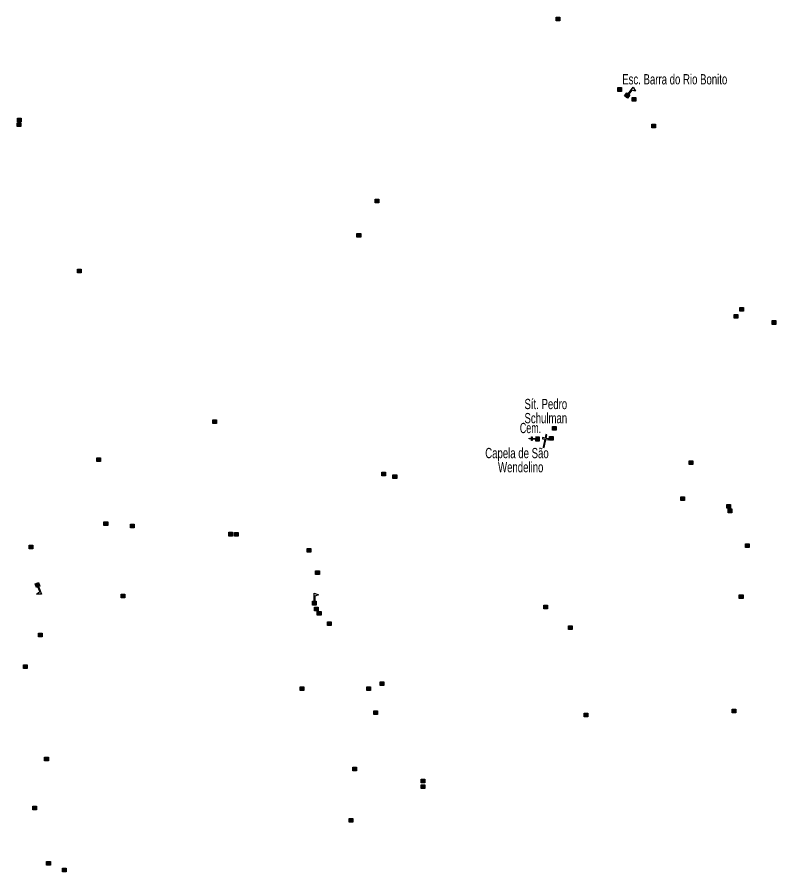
# Model space of a CAD drawing. Extents: x 647.8 to 672.9, y 6929.3 to 6957.3.
# Drawn here: x 648.14 to 654.07, y 6943.68 to 6950.35 of the extents above; entities that cross this region are included whole.
import ezdxf
from ezdxf.enums import TextEntityAlignment as Align

# ---------------------------------------------------------------- set-up
doc = ezdxf.new("R2010")
doc.units = 0
doc.header["$LTSCALE"] = 0.032
for name, color, linetype, lineweight in [('2', 7, 'Continuous', 25), ('20', 7, 'Continuous', 25), ('4', 7, 'Continuous', 25), ('6', 7, 'Continuous', 25)]:
    doc.layers.add(name, color=color, linetype=linetype, lineweight=lineweight)
doc.layers.add('61', color=7, linetype='Continuous')

msp = doc.modelspace()

# ---------------------------------------------------------------- hatches: boundary and pattern name
at = {"layer": '2'}
for points in [[(652.3521, 6950.3524), (652.3811, 6950.3524), (652.3811, 6950.3234), (652.3521, 6950.3234)], [(652.8326, 6949.8018), (652.8616, 6949.8018), (652.8616, 6949.7728), (652.8326, 6949.7728)], [(652.9445, 6949.725), (652.9735, 6949.725), (652.9735, 6949.696), (652.9445, 6949.696)], [(648.1465, 6949.5648), (648.1755, 6949.5648), (648.1755, 6949.5358), (648.1465, 6949.5358)], [(648.1443, 6949.5275), (648.1733, 6949.5275), (648.1733, 6949.4985), (648.1443, 6949.4985)], [(653.098, 6949.5166), (653.127, 6949.5166), (653.127, 6949.4876), (653.098, 6949.4876)], [(650.9393, 6948.9308), (650.9683, 6948.9308), (650.9683, 6948.9018), (650.9393, 6948.9018)], [(650.7967, 6948.6631), (650.8257, 6948.6631), (650.8257, 6948.6341), (650.7967, 6948.6341)], [(648.616, 6948.3845), (648.645, 6948.3845), (648.645, 6948.3555), (648.616, 6948.3555)], [(653.7408, 6948.0313), (653.7698, 6948.0313), (653.7698, 6948.0023), (653.7408, 6948.0023)], [(653.7847, 6948.0862), (653.8137, 6948.0862), (653.8137, 6948.0572), (653.7847, 6948.0572)], [(654.037, 6947.9831), (654.066, 6947.9831), (654.066, 6947.9541), (654.037, 6947.9541)], [(649.6712, 6947.2086), (649.7002, 6947.2086), (649.7002, 6947.1796), (649.6712, 6947.1796)], [(652.3214, 6947.156), (652.3504, 6947.156), (652.3504, 6947.127), (652.3214, 6947.127)], [(652.2995, 6947.0792), (652.3285, 6947.0792), (652.3285, 6947.0502), (652.2995, 6947.0502)], [(648.7674, 6946.9125), (648.7964, 6946.9125), (648.7964, 6946.8835), (648.7674, 6946.8835)], [(653.3898, 6946.8883), (653.4188, 6946.8883), (653.4188, 6946.8593), (653.3898, 6946.8593)], [(650.9897, 6946.8006), (651.0187, 6946.8006), (651.0187, 6946.7716), (650.9897, 6946.7716)], [(651.0775, 6946.7808), (651.1065, 6946.7808), (651.1065, 6946.7518), (651.0775, 6946.7518)], [(653.324, 6946.6075), (653.353, 6946.6075), (653.353, 6946.5785), (653.324, 6946.5785)], [(653.6838, 6946.5483), (653.7128, 6946.5483), (653.7128, 6946.5193), (653.6838, 6946.5193)], [(653.6926, 6946.5132), (653.7216, 6946.5132), (653.7216, 6946.4842), (653.6926, 6946.4842)], [(648.8222, 6946.4123), (648.8512, 6946.4123), (648.8512, 6946.3833), (648.8222, 6946.3833)], [(649.0284, 6946.3947), (649.0574, 6946.3947), (649.0574, 6946.3657), (649.0284, 6946.3657)], [(649.7963, 6946.3311), (649.8253, 6946.3311), (649.8253, 6946.3021), (649.7963, 6946.3021)], [(649.8402, 6946.3289), (649.8692, 6946.3289), (649.8692, 6946.2999), (649.8402, 6946.2999)], [(648.2387, 6946.2302), (648.2677, 6946.2302), (648.2677, 6946.2012), (648.2387, 6946.2012)], [(653.8286, 6946.2411), (653.8576, 6946.2411), (653.8576, 6946.2121), (653.8286, 6946.2121)], [(650.4084, 6946.2038), (650.4374, 6946.2038), (650.4374, 6946.1748), (650.4084, 6946.1748)], [(650.4742, 6946.0305), (650.5032, 6946.0305), (650.5032, 6946.0015), (650.4742, 6946.0015)], [(648.957, 6945.8475), (648.986, 6945.8475), (648.986, 6945.8185), (648.957, 6945.8185)], [(653.7803, 6945.8441), (653.8093, 6945.8441), (653.8093, 6945.8151), (653.7803, 6945.8151)], [(652.2556, 6945.7629), (652.2846, 6945.7629), (652.2846, 6945.7339), (652.2556, 6945.7339)], [(650.4654, 6945.7475), (650.4944, 6945.7475), (650.4944, 6945.7185), (650.4654, 6945.7185)], [(650.4873, 6945.7124), (650.5163, 6945.7124), (650.5163, 6945.6834), (650.4873, 6945.6834)], [(650.5663, 6945.6334), (650.5953, 6945.6334), (650.5953, 6945.6044), (650.5663, 6945.6044)], [(652.4465, 6945.6005), (652.4755, 6945.6005), (652.4755, 6945.5715), (652.4465, 6945.5715)], [(648.3111, 6945.5435), (648.3401, 6945.5435), (648.3401, 6945.5145), (648.3111, 6945.5145)], [(648.1948, 6945.2978), (648.2238, 6945.2978), (648.2238, 6945.2688), (648.1948, 6945.2688)], [(650.9766, 6945.164), (651.0056, 6945.164), (651.0056, 6945.135), (650.9766, 6945.135)], [(650.3535, 6945.1245), (650.3825, 6945.1245), (650.3825, 6945.0955), (650.3535, 6945.0955)], [(650.8735, 6945.1245), (650.9025, 6945.1245), (650.9025, 6945.0955), (650.8735, 6945.0955)], [(650.9283, 6944.938), (650.9573, 6944.938), (650.9573, 6944.909), (650.9283, 6944.909)], [(652.5693, 6944.9204), (652.5983, 6944.9204), (652.5983, 6944.8914), (652.5693, 6944.8914)], [(653.7255, 6944.9512), (653.7545, 6944.9512), (653.7545, 6944.9222), (653.7255, 6944.9222)], [(648.3593, 6944.576), (648.3883, 6944.576), (648.3883, 6944.547), (648.3593, 6944.547)], [(650.7638, 6944.497), (650.7928, 6944.497), (650.7928, 6944.468), (650.7638, 6944.468)], [(651.2969, 6944.4049), (651.3259, 6944.4049), (651.3259, 6944.3759), (651.2969, 6944.3759)], [(651.2969, 6944.361), (651.3259, 6944.361), (651.3259, 6944.332), (651.2969, 6944.332)], [(648.2672, 6944.1943), (648.2962, 6944.1943), (648.2962, 6944.1653), (648.2672, 6944.1653)], [(650.7353, 6944.0978), (650.7643, 6944.0978), (650.7643, 6944.0688), (650.7353, 6944.0688)], [(648.3747, 6943.7621), (648.4037, 6943.7621), (648.4037, 6943.7331), (648.3747, 6943.7331)], [(648.4975, 6943.7094), (648.5265, 6943.7094), (648.5265, 6943.6804), (648.4975, 6943.6804)]]:
    msp.add_hatch(color=256, dxfattribs=at).paths.add_polyline_path(points)
at = {"layer": '4'}
for points in [[(652.8849, 6949.7385), (652.9032, 6949.7623), (652.927, 6949.7441), (652.9087, 6949.7203)], [(648.3122, 6945.9399), (648.3229, 6945.9119), (648.2949, 6945.901), (648.2841, 6945.929)], [(650.4492, 6945.7634), (650.4492, 6945.7934), (650.4792, 6945.7934), (650.4792, 6945.7634)]]:
    msp.add_hatch(color=256, dxfattribs=at).paths.add_polyline_path(points)
at = {"layer": '6'}
for points in [[(652.1912, 6947.0629), (652.191, 6947.0579), (652.1635, 6947.0591), (652.163, 6947.0466), (652.158, 6947.0468), (652.1585, 6947.0593), (652.141, 6947.0599), (652.1412, 6947.0649), (652.1587, 6947.0643), (652.1593, 6947.0767), (652.1643, 6947.0765), (652.1637, 6947.064)], [(652.1905, 6947.0454), (652.2204, 6947.0441), (652.2217, 6947.0741), (652.1917, 6947.0754)]]:
    msp.add_hatch(color=256, dxfattribs=at).paths.add_polyline_path(points)

# ---------------------------------------------------------------- linework, layer by layer
at = {"layer": '2'}
for points in [[(652.3521, 6950.3524), (652.3811, 6950.3524), (652.3811, 6950.3234), (652.3521, 6950.3234)], [(652.8326, 6949.8018), (652.8616, 6949.8018), (652.8616, 6949.7728), (652.8326, 6949.7728)], [(652.9445, 6949.725), (652.9735, 6949.725), (652.9735, 6949.696), (652.9445, 6949.696)], [(648.1465, 6949.5648), (648.1755, 6949.5648), (648.1755, 6949.5358), (648.1465, 6949.5358)], [(648.1443, 6949.5275), (648.1733, 6949.5275), (648.1733, 6949.4985), (648.1443, 6949.4985)], [(653.098, 6949.5166), (653.127, 6949.5166), (653.127, 6949.4876), (653.098, 6949.4876)], [(650.9393, 6948.9308), (650.9683, 6948.9308), (650.9683, 6948.9018), (650.9393, 6948.9018)], [(650.7967, 6948.6631), (650.8257, 6948.6631), (650.8257, 6948.6341), (650.7967, 6948.6341)], [(648.616, 6948.3845), (648.645, 6948.3845), (648.645, 6948.3555), (648.616, 6948.3555)], [(653.7408, 6948.0313), (653.7698, 6948.0313), (653.7698, 6948.0023), (653.7408, 6948.0023)], [(653.7847, 6948.0862), (653.8137, 6948.0862), (653.8137, 6948.0572), (653.7847, 6948.0572)], [(654.037, 6947.9831), (654.066, 6947.9831), (654.066, 6947.9541), (654.037, 6947.9541)], [(649.6712, 6947.2086), (649.7002, 6947.2086), (649.7002, 6947.1796), (649.6712, 6947.1796)], [(652.3214, 6947.156), (652.3504, 6947.156), (652.3504, 6947.127), (652.3214, 6947.127)], [(652.2995, 6947.0792), (652.3285, 6947.0792), (652.3285, 6947.0502), (652.2995, 6947.0502)], [(648.7674, 6946.9125), (648.7964, 6946.9125), (648.7964, 6946.8835), (648.7674, 6946.8835)], [(653.3898, 6946.8883), (653.4188, 6946.8883), (653.4188, 6946.8593), (653.3898, 6946.8593)], [(650.9897, 6946.8006), (651.0187, 6946.8006), (651.0187, 6946.7716), (650.9897, 6946.7716)], [(651.0775, 6946.7808), (651.1065, 6946.7808), (651.1065, 6946.7518), (651.0775, 6946.7518)], [(653.324, 6946.6075), (653.353, 6946.6075), (653.353, 6946.5785), (653.324, 6946.5785)], [(653.6838, 6946.5483), (653.7128, 6946.5483), (653.7128, 6946.5193), (653.6838, 6946.5193)], [(653.6926, 6946.5132), (653.7216, 6946.5132), (653.7216, 6946.4842), (653.6926, 6946.4842)], [(648.8222, 6946.4123), (648.8512, 6946.4123), (648.8512, 6946.3833), (648.8222, 6946.3833)], [(649.0284, 6946.3947), (649.0574, 6946.3947), (649.0574, 6946.3657), (649.0284, 6946.3657)], [(649.7963, 6946.3311), (649.8253, 6946.3311), (649.8253, 6946.3021), (649.7963, 6946.3021)], [(649.8402, 6946.3289), (649.8692, 6946.3289), (649.8692, 6946.2999), (649.8402, 6946.2999)], [(648.2387, 6946.2302), (648.2677, 6946.2302), (648.2677, 6946.2012), (648.2387, 6946.2012)], [(653.8286, 6946.2411), (653.8576, 6946.2411), (653.8576, 6946.2121), (653.8286, 6946.2121)], [(650.4084, 6946.2038), (650.4374, 6946.2038), (650.4374, 6946.1748), (650.4084, 6946.1748)], [(650.4742, 6946.0305), (650.5032, 6946.0305), (650.5032, 6946.0015), (650.4742, 6946.0015)], [(648.957, 6945.8475), (648.986, 6945.8475), (648.986, 6945.8185), (648.957, 6945.8185)], [(653.7803, 6945.8441), (653.8093, 6945.8441), (653.8093, 6945.8151), (653.7803, 6945.8151)], [(652.2556, 6945.7629), (652.2846, 6945.7629), (652.2846, 6945.7339), (652.2556, 6945.7339)], [(650.4654, 6945.7475), (650.4944, 6945.7475), (650.4944, 6945.7185), (650.4654, 6945.7185)], [(650.4873, 6945.7124), (650.5163, 6945.7124), (650.5163, 6945.6834), (650.4873, 6945.6834)], [(650.5663, 6945.6334), (650.5953, 6945.6334), (650.5953, 6945.6044), (650.5663, 6945.6044)], [(652.4465, 6945.6005), (652.4755, 6945.6005), (652.4755, 6945.5715), (652.4465, 6945.5715)], [(648.3111, 6945.5435), (648.3401, 6945.5435), (648.3401, 6945.5145), (648.3111, 6945.5145)], [(648.1948, 6945.2978), (648.2238, 6945.2978), (648.2238, 6945.2688), (648.1948, 6945.2688)], [(650.9766, 6945.164), (651.0056, 6945.164), (651.0056, 6945.135), (650.9766, 6945.135)], [(650.3535, 6945.1245), (650.3825, 6945.1245), (650.3825, 6945.0955), (650.3535, 6945.0955)], [(650.8735, 6945.1245), (650.9025, 6945.1245), (650.9025, 6945.0955), (650.8735, 6945.0955)], [(650.9283, 6944.938), (650.9573, 6944.938), (650.9573, 6944.909), (650.9283, 6944.909)], [(652.5693, 6944.9204), (652.5983, 6944.9204), (652.5983, 6944.8914), (652.5693, 6944.8914)], [(653.7255, 6944.9512), (653.7545, 6944.9512), (653.7545, 6944.9222), (653.7255, 6944.9222)], [(648.3593, 6944.576), (648.3883, 6944.576), (648.3883, 6944.547), (648.3593, 6944.547)], [(650.7638, 6944.497), (650.7928, 6944.497), (650.7928, 6944.468), (650.7638, 6944.468)], [(651.2969, 6944.4049), (651.3259, 6944.4049), (651.3259, 6944.3759), (651.2969, 6944.3759)], [(651.2969, 6944.361), (651.3259, 6944.361), (651.3259, 6944.332), (651.2969, 6944.332)], [(648.2672, 6944.1943), (648.2962, 6944.1943), (648.2962, 6944.1653), (648.2672, 6944.1653)], [(650.7353, 6944.0978), (650.7643, 6944.0978), (650.7643, 6944.0688), (650.7353, 6944.0688)], [(648.3747, 6943.7621), (648.4037, 6943.7621), (648.4037, 6943.7331), (648.3747, 6943.7331)], [(648.4975, 6943.7094), (648.5265, 6943.7094), (648.5265, 6943.6804), (648.4975, 6943.6804)]]:
    msp.add_lwpolyline(points, close=True, dxfattribs=at)
at = {"layer": '20'}
for points in [[(652.2725, 6947.0642), (652.2782, 6947.0916), (652.2704, 6947.0932), (652.2646, 6947.0658)], [(652.2646, 6947.0658), (652.2451, 6947.0699), (652.2433, 6947.0616), (652.2629, 6947.0575), (652.2498, 6946.9954)], [(652.2498, 6946.9954), (652.2576, 6946.9937), (652.2707, 6947.0559)], [(652.2707, 6947.0559), (652.2903, 6947.0517), (652.292, 6947.0601), (652.2725, 6947.0642)]]:
    msp.add_lwpolyline(points, dxfattribs=at)
at = {"layer": '4'}
for p, q in [((652.9131, 6949.7547), (652.9171, 6949.7517)), ((648.3113, 6945.9074), (648.3066, 6945.9056)), ((650.4617, 6945.7934), (650.4667, 6945.7934))]:
    msp.add_line(p, q, dxfattribs=at)
for points in [[(652.8849, 6949.7385), (652.9032, 6949.7623), (652.927, 6949.7441), (652.9087, 6949.7203)], [(652.9131, 6949.7547), (652.9511, 6949.8044), (652.9713, 6949.7732), (652.9411, 6949.7831), (652.9171, 6949.7517)], [(648.3122, 6945.9399), (648.3229, 6945.9119), (648.2949, 6945.901), (648.2841, 6945.929)], [(648.3113, 6945.9074), (648.3337, 6945.849), (648.2966, 6945.8481), (648.3208, 6945.8687), (648.3066, 6945.9056)], [(650.4617, 6945.7934), (650.4617, 6945.8559), (650.4967, 6945.8434), (650.4667, 6945.8329), (650.4667, 6945.7934)], [(650.4492, 6945.7634), (650.4492, 6945.7934), (650.4792, 6945.7934), (650.4792, 6945.7634)]]:
    msp.add_lwpolyline(points, close=True, dxfattribs=at)
at = {"layer": '6'}
for points in [[(652.1912, 6947.0629), (652.191, 6947.0579), (652.1635, 6947.0591), (652.163, 6947.0466), (652.158, 6947.0468), (652.1585, 6947.0593), (652.141, 6947.0599), (652.1412, 6947.0649), (652.1587, 6947.0643), (652.1593, 6947.0767), (652.1643, 6947.0765), (652.1637, 6947.064)], [(652.1905, 6947.0454), (652.2204, 6947.0441), (652.2217, 6947.0741), (652.1917, 6947.0754)]]:
    msp.add_lwpolyline(points, close=True, dxfattribs=at)

# ---------------------------------------------------------------- texts
at = {"layer": '61', "width": 0.7}
for s, p in [('Esc. Barra do Rio Bonito', (652.8667, 6949.8271)), ('Sít. Pedro', (652.1039, 6947.2925)), ('Schulman', (652.1039, 6947.1825))]:
    msp.add_text(s, height=0.08, dxfattribs=at).set_placement(p)
at = {"layer": '61'}
for s, width, p in [('Cem.', 0.65, (652.2339, 6947.1052)), ('Capela de São', 0.7, (652.293, 6946.9096)), ('   Wendelino  ', 0.7, (652.293, 6946.7996))]:
    msp.add_text(s, height=0.08, dxfattribs=dict(at, width=width)).set_placement(p, align=Align.RIGHT)

doc.saveas('drawing.dxf')
